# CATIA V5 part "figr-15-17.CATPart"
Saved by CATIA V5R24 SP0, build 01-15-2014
Part number: Part1
Bounding box of the stored display mesh (mm): x -46.56 to 46.56, y -26.965 to 25.965, z 0 to 40
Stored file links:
  D:\KAVITA\CATIA V5-6R2014 Project_ Kavita\CATIA V5-6R2014_partfiles\Partfiles\c15_catia_v5-6r2014_prt\figr-15-17.CATPart
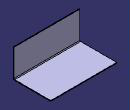
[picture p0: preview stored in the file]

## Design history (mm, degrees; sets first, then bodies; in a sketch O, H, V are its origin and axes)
SheetMetalParameters1: Thickness 1, BendRadius 1, KFactor 0.325257 {= log(min(100,max(20*SheetMetalParameters1.BendRadius,SheetMetalParameters1.Thickness)/SheetMetalParameters1.Thickness))/log(100)/2}, ReliefRadialLength 1, ReliefAxialLength 2, MinimumBendRadius 0
Body1 (main body)
  Sketch1 on xy-plane, origin (0, 0, 0), H (1, 0, 0), V (0, 1, 0)
    line L1 (-46.5596, 25.9646) -> (46.5596, 25.9646)
    line L2 (46.5596, 25.9646) -> (46.5596, -25.9646)
    line L3 (46.5596, -25.9646) -> (-46.5596, -25.9646)
    line L4 (-46.5596, -25.9646) -> (-46.5596, 25.9646)
    horizontal: L1 H, L3 H
    vertical: L2 V, L4 V
    symmetry: L1 L3 H, L4 L2 V
  Wall1: Thickness 1, Profile Sketch1
  d_NewWallOnEdge1: NewWallOnEdge_Edge edge [face of Wall1 | face of Wall1], NewWallOnEdge_Length 40, NewWallOnEdge_HeightLimitOffset 0, NewWallOnEdge_WidthOffset1 0, NewWallOnEdge_WidthOffset2 0, NewWallOnEdge_Angle 90, NewWallOnEdge_BendRadiusValue 1 {= SheetMetalParameters1.BendRadius}, NewWallOnEdge_BendTable SheetMetalParameters1, KFacteur 0.325257 {= log(min(100,max(20*d_NewWallOnEdge1.Radius,SheetMetalParameters1.Thickness)/SheetMetalParameters1.Thickness))/log(100)/2}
